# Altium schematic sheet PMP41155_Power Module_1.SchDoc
size 431 x 279 mm; Date: Not shown in title block; ApprovedBy: Not shown in title block; CheckedBy: Not shown in title block; Author: Not shown in title block; CompanyName: Not shown in title block; Engineer: Not shown in title block; Organization: Not shown in title block; Address1: Not shown in title block; Address2: Not shown in title block; Address3: Not shown in title block; Address4: Not shown in title block; DocumentNumber: 1; Revision: Use project parameter SCH_Rev; SheetNumber: 2; SheetTotal: 2; PageSetup: Record=PageOptions¦CenterHorizontal=True¦CenterVertical=True¦PrintScale=1.00¦XCorrection=1.00¦YCorrection=1.00¦PrintKind=0¦BorderSize=5000000¦LeftOffset=0¦BottomOffset=0¦Orientation=2¦PaperLength=1000¦PaperWidth=1000¦Scale=100¦PaperSource=15¦PrintQuality=600¦MediaType=1¦DitherType=10¦PaperKind=Letter¦PrintScaleMode=1
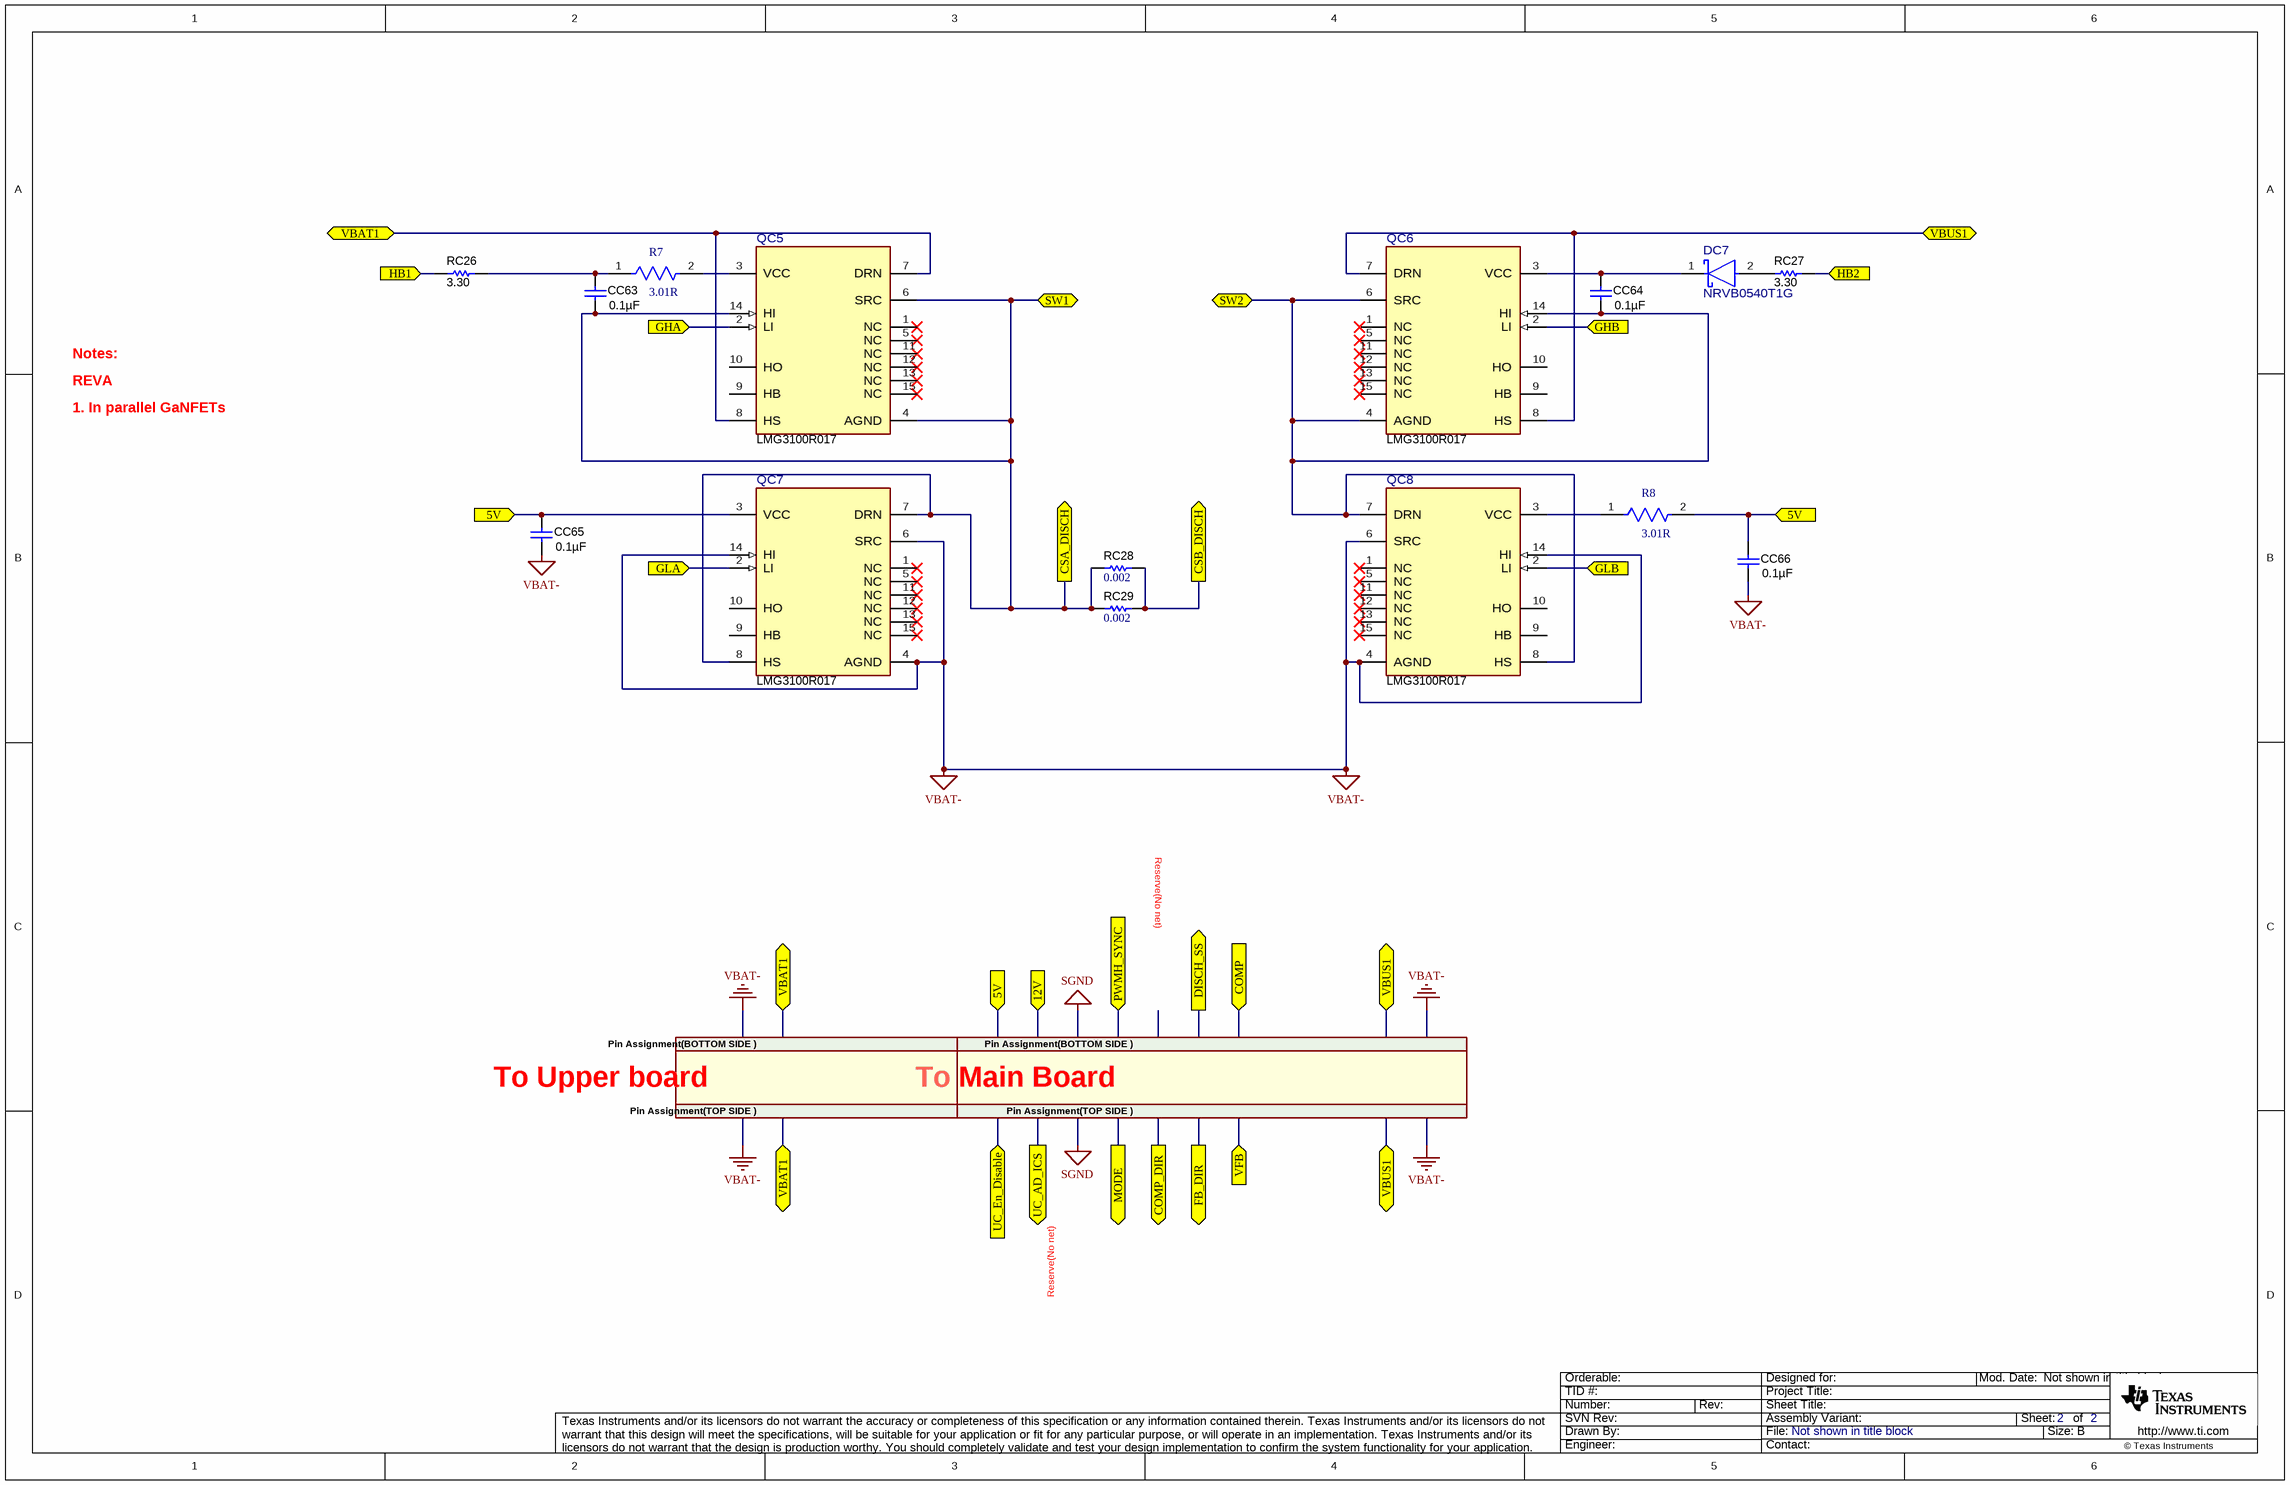
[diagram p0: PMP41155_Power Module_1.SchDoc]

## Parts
CC63  ValueDisplayed: 0.1µF  [0402]  (hidden comment: GCM155R71C104JA55D)
CC64  ValueDisplayed: 0.1µF  [0402]  (hidden comment: GCM155R71C104JA55D)
CC65  ValueDisplayed: 0.1µF  [0402]  (hidden comment: GCM155R71C104JA55D)
CC66  ValueDisplayed: 0.1µF  [0402]  (hidden comment: GCM155R71C104JA55D)
DC7  NRVB0540T1G  [FP-NRVB0540T1G_SOD-123-MFG]
QC5  LMG3100R017  [VBE0015A-MFG]
QC6  LMG3100R017  [VBE0015A-MFG]
QC7  LMG3100R017  [VBE0015A-MFG]
QC8  LMG3100R017  [VBE0015A-MFG]
R7  Resistance: 3.01R  [FP-CRCW0402-e3-MFG]  (hidden comment: CRCW04023R01FNED)
R8  Resistance: 3.01R  [FP-CRCW0402-e3-MFG]  (hidden comment: CRCW04023R01FNED)
RC26  ValueDisplayed: 3.30  [1206]  (hidden comment: RC1206FR-073R3L)
RC27  ValueDisplayed: 3.30  [1206]  (hidden comment: RC1206FR-073R3L)
RC28  ValueDisplayed: 0.002  [0508]  (hidden comment: KRL2012E-M-R002-G-T5)
RC29  ValueDisplayed: 0.002  [0508]  (hidden comment: KRL2012E-M-R002-G-T5)

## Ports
5V (in), 12V (in), COMP (in), COMP_DIR (out), CSA_DISCH (out), CSB_DISCH (out), DISCH_SS (out), FB_DIR (out), GHA (in), GHB (in), GLA (in), GLB (in), HB1 (in), HB2 (in), MODE (out), PWMH_SYNC (in), SW1 (bidir), SW2 (bidir), UC_AD_ICS (out), UC_En_Disable (in), VBAT1 (bidir), VBUS1 (bidir), VFB (in)

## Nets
VBAT-: CC65.2 CC66.2 QC7.4(AGND) QC7.6(SRC) QC7.14(HI) QC8.4(AGND) QC8.6(SRC) QC8.14(HI)
5V: CC65.1 CC66.1 QC7.3(VCC) R8.2 ; port 5V
CSA_DISCH: CC63.2 QC5.4(AGND) QC5.6(SRC) QC5.14(HI) QC7.7(DRN) QC7.8(HS) RC28.1 RC29.1 ; port SW1, port CSA_DISCH
CSB_DISCH: RC28.2 RC29.2 ; port CSB_DISCH
GHA: QC5.2(LI) ; port GHA
GHB: QC6.2(LI) ; port GHB
GLA: QC7.2(LI) ; port GLA
GLB: QC8.2(LI) ; port GLB
HB1: RC26.1 ; port HB1
HB2: RC27.2 ; port HB2
SW2: CC64.2 QC6.4(AGND) QC6.6(SRC) QC6.14(HI) QC8.7(DRN) QC8.8(HS) ; port SW2
VBAT1: QC5.7(DRN) QC5.8(HS) ; port VBAT1
VBUS1: QC6.7(DRN) QC6.8(HS) ; port VBUS1
NetCC63_1: CC63.1 R7.1 RC26.2
NetCC64_1: CC64.1 DC7.1(CATHODE) QC6.3(VCC)
NetDC7_2: DC7.2(ANODE) RC27.1
NetQC5_3: QC5.3(VCC) R7.2
NetQC8_3: QC8.3(VCC) R8.1

Not connected (* = marked no-connect by the designer): QC5 1(NC)* 5(NC)* 9(HB) 10(HO) 11(NC)* 12(NC)* 13(NC)* 15(NC)*; QC6 1(NC)* 5(NC)* 9(HB) 10(HO) 11(NC)* 12(NC)* 13(NC)* 15(NC)*; QC7 1(NC)* 5(NC)* 9(HB) 10(HO) 11(NC)* 12(NC)* 13(NC)* 15(NC)*; QC8 1(NC)* 5(NC)* 9(HB) 10(HO) 11(NC)* 12(NC)* 13(NC)* 15(NC)*

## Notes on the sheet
- Notes:
- 1. In parallel GaNFETs
- REVA
- Reserve(No net)
- To Upper board
- Pin Assignment(BOTTOM SIDE )
- Pin Assignment(TOP SIDE )
- To Main Board

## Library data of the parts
CC63-CC66 = CMP-0080702-1: CAP, CERM, 0.1 µF, 16 V,+/- 5%, X7R, AEC-Q200 Grade 1, 0402; Manufacturer: MuRata; Cap_F: 100nF; SizeAreaWB_mm2: 3; SizeArea_mm2: 0.5; AEC Qualified: Y; AEC Category: Q200; Value: 0.1uF; TaMax_C: 125°C; SizeZ_mm: 0.6; AEC Grade: 1; Polarized: N; TaMin_C: -55°C; VDC_V: 16V; U/M: EA
DC7 = CMP-0090564-1: Diode Schottky 40V 500mA Surface Mount SOD-123; Manufacturer: On Semiconductor; Max Surge Forward Current: 5.5A; Standoff Height: 0mm; Import Ts: 1521847448; AEC Grade: Grade 0; AEC Qualified: Yes; Peak Reverse Current: 20uA; SizeZ_mm: 1.35mm; TJmax_C: 150°C; Ciiva Ids: 822523; Forward Current: 0.5A
QC5-QC8 = CMP-0037654-1: 100-V, 64-A GaN with Integrated Driver; Manufacturer: Texas Instruments; SizeZ_mm: 0.85mm; AEC Qualified: No; Max Supply Voltage: 5.25V; Min Supply Voltage: 4.75V; Nominal Supply Current: 3mA; Number Of Drivers: 1; Propagation Delay: 55ns; Standoff Height: 0mm; TJmax_C: +125°C
R7 R8 = CMP-02407-004899-1: RES Thick Film, 3.01Ω, 1%, 0.063W, 200ppm/°C, 0402; Max Power Dissipation: 63mW; Voltage Rating (DC): 50V
RC26 RC27 = CMP-0018270-2: RES, 3.30, 1%, 0.25 W, 1206; Manufacturer: Yageo America; Power_W: 250mW; TempCo: 200 ppm/C; Value_Code: 3R30; U/M: EA; Value: 3.30; Res_ohm: 3.3; SizeX_mm: 3.2; SizeY_mm: 1.6; SizeZ_mm: 1.35; Value2: 0.25W; SizeArea_mm2: 5.12; VDC_V: 200V; AEC Category: Q200
RC28 RC29 = CMP-0015357-3: RES, 0.002, 2%, 1 W, 0508; Manufacturer: Susumu Co Ltd; Power_W: 1W; TempCo: 100 ppm/C; SizeAreaWB_mm2: 6.75; Value_Code: 2L000; U/M: EA; Value: 0.002; Res_ohm: 2m; SizeX_mm: 1.25; SizeY_mm: 2; SizeZ_mm: 1; SizeArea_mm2: 2.5; AEC Category: Q200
